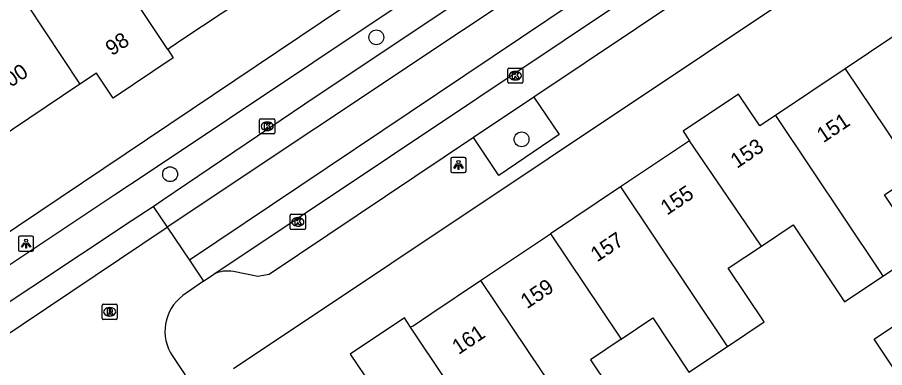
# Model space of a CAD drawing. Extents: x 158352 to 159489, y 383828 to 384597.
# Drawn here: x 158835 to 158892.1, y 384217.6 to 384240.7 of the extents above; entities that cross this region are included whole.
import ezdxf

# ---------------------------------------------------------------- set-up
doc = ezdxf.new("R2010")
doc.units = 0
for name, color, linetype in [('IMGEO_Boom', 7, 'Continuous'), ('IMGEO_Kolk', 7, 'Continuous'), ('IMGEO_Lichtpunt', 7, 'Continuous'), ('IMGEO_Pand', 7, 'Continuous'), ('IMGEO_Pand_nummerreeks', 7, 'Continuous'), ('IMGEO_Parkeervlak_open', 7, 'Continuous'), ('IMGEO_Rijbaan_lokaal_gesloten', 7, 'Continuous'), ('IMGEO_Rijbaan_lokaal_open', 7, 'Continuous'), ('IMGEO_Rioolput', 7, 'Continuous'), ('IMGEO_Voetpad_open', 7, 'Continuous')]:
    doc.layers.add(name, color=color, linetype=linetype)

msp = doc.modelspace()

# ---------------------------------------------------------------- linework, layer by layer
at = {"layer": 'IMGEO_Boom'}
for centre in [(158858.595, 384239.407), (158868.161, 384232.684), (158845.022, 384230.389)]:
    msp.add_circle(centre, 0.489, dxfattribs=at)
at = {"layer": 'IMGEO_Kolk'}
for p, q in [((158867.249, 384236.455), (158867.249, 384237.307)), ((158867.324, 384237.381), (158868.176, 384237.381)), ((158867.737, 384237.161), (158867.762, 384237.161)), ((158868.25, 384237.307), (158868.25, 384236.455)), ((158867.76, 384236.601), (158867.735, 384236.601)), ((158868.176, 384236.381), (158867.324, 384236.381)), ((158850.914, 384233.12), (158850.914, 384233.972)), ((158850.989, 384234.046), (158851.841, 384234.046)), ((158851.402, 384233.826), (158851.427, 384233.826)), ((158851.915, 384233.972), (158851.915, 384233.12)), ((158851.425, 384233.266), (158851.4, 384233.266)), ((158851.841, 384233.046), (158850.989, 384233.046)), ((158852.928, 384226.819), (158852.928, 384227.671)), ((158853.003, 384227.745), (158853.855, 384227.745)), ((158853.416, 384227.525), (158853.441, 384227.525)), ((158853.929, 384227.671), (158853.929, 384226.819)), ((158853.439, 384226.965), (158853.414, 384226.965)), ((158853.855, 384226.745), (158853.003, 384226.745))]:
    msp.add_line(p, q, dxfattribs=at)
for points in [[(158867.249, 384236.455), (158867.249, 384237.307)], [(158867.324, 384237.381), (158868.176, 384237.381)], [(158867.57, 384237.081), (158867.693, 384237.081), (158867.693, 384236.93), (158867.823, 384237.081), (158867.987, 384237.081), (158867.841, 384236.93), (158867.994, 384236.681), (158867.842, 384236.681), (158867.757, 384236.845), (158867.693, 384236.778), (158867.693, 384236.681), (158867.57, 384236.681), (158867.57, 384237.081)], [(158868.25, 384237.307), (158868.25, 384236.455)], [(158868.176, 384236.381), (158867.324, 384236.381)], [(158850.914, 384233.12), (158850.914, 384233.972)], [(158850.989, 384234.046), (158851.841, 384234.046)], [(158851.235, 384233.746), (158851.358, 384233.746), (158851.358, 384233.595), (158851.488, 384233.746), (158851.652, 384233.746), (158851.506, 384233.595), (158851.659, 384233.346), (158851.507, 384233.346), (158851.422, 384233.51), (158851.358, 384233.443), (158851.358, 384233.346), (158851.235, 384233.346), (158851.235, 384233.746)], [(158851.915, 384233.972), (158851.915, 384233.12)], [(158851.841, 384233.046), (158850.989, 384233.046)], [(158852.928, 384226.819), (158852.928, 384227.671)], [(158853.003, 384227.745), (158853.855, 384227.745)], [(158853.249, 384227.445), (158853.372, 384227.445), (158853.372, 384227.294), (158853.502, 384227.445), (158853.666, 384227.445), (158853.52, 384227.294), (158853.673, 384227.045), (158853.521, 384227.045), (158853.436, 384227.209), (158853.372, 384227.142), (158853.372, 384227.045), (158853.249, 384227.045), (158853.249, 384227.445)], [(158853.929, 384227.671), (158853.929, 384226.819)], [(158853.855, 384226.745), (158853.003, 384226.745)]]:
    msp.add_lwpolyline(points, dxfattribs=at)
for centre, start, end in [((158867.326, 384237.305), 91.552, 178.448), ((158867.326, 384237.305), 91.552, 178.448), ((158868.174, 384237.305), 1.552, 88.448), ((158868.174, 384237.305), 1.552, 88.448), ((158867.326, 384236.457), 181.552, 268.448), ((158867.326, 384236.457), 181.552, 268.448), ((158868.174, 384236.457), 271.552, 358.448), ((158868.174, 384236.457), 271.552, 358.448), ((158850.991, 384233.97), 91.552, 178.448), ((158850.991, 384233.97), 91.552, 178.448), ((158851.839, 384233.97), 1.552, 88.448), ((158851.839, 384233.97), 1.552, 88.448), ((158850.991, 384233.122), 181.552, 268.448), ((158850.991, 384233.122), 181.552, 268.448), ((158851.839, 384233.122), 271.552, 358.448), ((158851.839, 384233.122), 271.552, 358.448), ((158853.005, 384227.669), 91.552, 178.448), ((158853.005, 384227.669), 91.552, 178.448), ((158853.853, 384227.669), 1.552, 88.448), ((158853.853, 384227.669), 1.552, 88.448), ((158853.005, 384226.821), 181.552, 268.448), ((158853.005, 384226.821), 181.552, 268.448), ((158853.853, 384226.821), 271.552, 358.448), ((158853.853, 384226.821), 271.552, 358.448)]:
    msp.add_arc(centre, 0.0765, start, end, dxfattribs=at)
for centre, major_axis, ratio, start_param, end_param in [((158867.736, 384236.881), (-0.387, 0.002), 0.722429, 4.712389, 7.853982), ((158867.761, 384236.881), (-0.39, 0.002), 0.717154, 1.570796, 4.712389), ((158851.401, 384233.546), (-0.387, 0.002), 0.722429, 4.712389, 7.853982), ((158851.426, 384233.546), (-0.39, 0.002), 0.717154, 1.570796, 4.712389), ((158853.415, 384227.245), (-0.387, 0.002), 0.722429, 4.712389, 7.853982), ((158853.44, 384227.245), (-0.39, 0.002), 0.717154, 1.570796, 4.712389)]:
    msp.add_ellipse(centre, major_axis=major_axis, ratio=ratio, start_param=start_param, end_param=end_param, dxfattribs=at)
at = {"layer": 'IMGEO_Lichtpunt'}
for p, q in [((158863.51, 384231.398), (158863.51, 384230.591)), ((158863.51, 384231.398), (158863.51, 384230.591)), ((158864.412, 384231.493), (158863.604, 384231.493)), ((158864.412, 384231.493), (158863.604, 384231.493)), ((158864.506, 384230.591), (158864.506, 384231.398)), ((158864.506, 384230.591), (158864.506, 384231.398)), ((158863.604, 384230.497), (158864.412, 384230.497)), ((158863.604, 384230.497), (158864.412, 384230.497)), ((158835.036, 384226.212), (158835.036, 384225.405)), ((158835.036, 384226.212), (158835.036, 384225.405)), ((158835.938, 384226.307), (158835.13, 384226.307)), ((158835.938, 384226.307), (158835.13, 384226.307)), ((158836.032, 384225.405), (158836.032, 384226.212)), ((158836.032, 384225.405), (158836.032, 384226.212)), ((158835.13, 384225.311), (158835.938, 384225.311)), ((158835.13, 384225.311), (158835.938, 384225.311))]:
    msp.add_line(p, q, dxfattribs=at)
for points in [[(158863.884, 384231.062), (158863.923, 384231.034), (158863.735, 384230.772), (158863.697, 384230.799), (158863.884, 384231.062)], [(158863.986, 384231.014), (158864.033, 384231.014), (158864.033, 384230.692), (158863.986, 384230.692), (158863.986, 384231.014)], [(158864.096, 384231.034), (158864.134, 384231.061), (158864.321, 384230.799), (158864.282, 384230.771), (158864.096, 384231.034)], [(158835.41, 384225.876), (158835.449, 384225.848), (158835.261, 384225.586), (158835.223, 384225.613), (158835.41, 384225.876)], [(158835.512, 384225.828), (158835.559, 384225.828), (158835.559, 384225.506), (158835.512, 384225.506), (158835.512, 384225.828)], [(158835.622, 384225.848), (158835.66, 384225.875), (158835.847, 384225.613), (158835.808, 384225.585), (158835.622, 384225.848)]]:
    msp.add_lwpolyline(points, dxfattribs=at)
for centre in [(158864.009, 384231.196), (158835.535, 384226.01)]:
    msp.add_circle(centre, 0.0994, dxfattribs=at)
for centre, start, end in [((158863.604, 384231.398), 90, 180), ((158863.604, 384231.398), 90, 180), ((158864.412, 384231.398), 0, 90), ((158864.412, 384231.398), 0, 90), ((158863.604, 384230.591), 180, 270), ((158863.604, 384230.591), 180, 270), ((158864.412, 384230.591), 270, 0), ((158864.412, 384230.591), 270, 360), ((158835.13, 384226.212), 90, 180), ((158835.13, 384226.212), 90, 180), ((158835.938, 384226.212), 0, 90), ((158835.938, 384226.212), 0, 90), ((158835.13, 384225.405), 180, 270), ((158835.13, 384225.405), 180, 270), ((158835.938, 384225.405), 270, 0), ((158835.938, 384225.405), 270, 360)]:
    msp.add_arc(centre, 0.0946, start, end, dxfattribs=at)
at = {"layer": 'IMGEO_Pand'}
for points in [[(158832.074, 384246.881), (158839.085, 384236.32)], [(158844.858, 384238.609), (158840.338, 384245.418)], [(158849.731, 384241.867), (158845.861, 384239.28), (158845.017, 384238.715), (158844.858, 384238.609)], [(158894.087, 384240.426), (158889.48, 384237.342)], [(158844.858, 384238.609), (158845.229, 384238.05), (158841.271, 384235.391), (158840.161, 384237.042), (158839.085, 384236.32)], [(158889.48, 384237.342), (158884.873, 384234.258)], [(158889.48, 384237.342), (158893.973, 384230.631), (158894.123, 384230.406)], [(158839.085, 384236.32), (158833.473, 384232.558)], [(158884.873, 384234.258), (158883.855, 384233.577), (158882.455, 384235.669), (158878.797, 384233.22), (158879.219, 384232.59)], [(158884.873, 384234.258), (158891.756, 384223.975), (158891.961, 384223.669)], [(158879.219, 384232.59), (158874.68, 384229.551)], [(158883.96, 384225.655), (158883.857, 384225.809), (158879.219, 384232.59)], [(158891.961, 384223.669), (158894.496, 384225.366), (158892.051, 384229.019), (158894.123, 384230.406)], [(158874.68, 384229.551), (158870.073, 384226.467)], [(158874.68, 384229.551), (158881.64, 384219.152), (158881.717, 384219.038)], [(158883.96, 384225.655), (158886.038, 384227.045), (158889.431, 384221.975), (158891.961, 384223.669)], [(158865.465, 384223.383), (158870.073, 384226.467)], [(158870.073, 384226.467), (158874.595, 384219.711), (158874.72, 384219.524)], [(158881.717, 384219.038), (158884.14, 384220.66), (158881.776, 384224.193), (158883.96, 384225.655)], [(158860.858, 384220.299), (158861.016, 384220.405), (158862.19, 384221.191), (158865.465, 384223.383)], [(158865.465, 384223.383), (158871.557, 384214.283), (158872.492, 384212.886)], [(158860.858, 384220.299), (158860.447, 384220.913), (158856.885, 384218.53), (158858.292, 384216.428), (158857.246, 384215.728)], [(158874.72, 384219.524), (158876.795, 384220.913), (158879.185, 384217.343), (158881.717, 384219.038)], [(158895.499, 384218.383), (158898.48, 384213.932), (158896.151, 384212.372), (158893.17, 384216.823), (158891.373, 384219.507), (158893.703, 384221.067)], [(158865.517, 384213.338), (158865.421, 384213.482), (158860.858, 384220.299)], [(158874.72, 384219.524), (158872.692, 384218.166), (158875.07, 384214.612), (158874.875, 384214.481)]]:
    msp.add_lwpolyline(points, dxfattribs=at)
at = {"layer": 'IMGEO_Parkeervlak_open'}
msp.add_lwpolyline([(158868.973, 384235.474), (158864.997, 384232.808)], dxfattribs=at)
at = {"layer": 'IMGEO_Rijbaan_lokaal_gesloten'}
for points in [[(158928.875, 384277.975), (158927.924, 384279.398), (158875.348, 384244.245), (158846.287, 384224.725)], [(158847.89, 384223.805), (158928.741, 384277.867)], [(158843.894, 384228.271), (158844.531, 384228.697), (158853.892, 384235.025), (158913.401, 384274.791)], [(158913.401, 384274.791), (158914.324, 384273.367), (158910.948, 384271.094), (158874.134, 384246.446), (158844.821, 384226.897)], [(158831.156, 384219.806), (158832.496, 384220.707), (158842.526, 384227.357), (158843.894, 384228.271)], [(158843.894, 384228.271), (158844.821, 384226.897)], [(158832.123, 384218.384), (158844.821, 384226.897)], [(158847.222, 384223.339), (158847.89, 384223.805)]]:
    msp.add_lwpolyline(points, dxfattribs=at)
at = {"layer": 'IMGEO_Rijbaan_lokaal_open'}
for points in [[(158844.821, 384226.897), (158846.287, 384224.725)], [(158846.287, 384224.725), (158847.222, 384223.339)], [(158847.222, 384223.339), (158845.858, 384222.389)], [(158845.198, 384218.378), (158846.791, 384215.962)]]:
    msp.add_lwpolyline(points, dxfattribs=at)
msp.add_arc((158847.609, 384220.041), 2.929, 126.7155, 214.5962, dxfattribs=at)
at = {"layer": 'IMGEO_Rioolput'}
for p, q in [((158840.54, 384220.893), (158840.54, 384221.745)), ((158840.615, 384221.819), (158841.467, 384221.819)), ((158841.541, 384221.745), (158841.541, 384220.893)), ((158841.028, 384221.599), (158841.053, 384221.599)), ((158841.467, 384220.819), (158840.615, 384220.819)), ((158841.051, 384221.039), (158841.026, 384221.039))]:
    msp.add_line(p, q, dxfattribs=at)
for points in [[(158840.54, 384220.893), (158840.54, 384221.745)], [(158840.615, 384221.819), (158841.467, 384221.819)], [(158841.541, 384221.745), (158841.541, 384220.893)], [(158841.129, 384221.517), (158840.877, 384221.519), (158840.877, 384221.119)], [(158840.877, 384221.119), (158841.001, 384221.119), (158841.001, 384221.281), (158841.012, 384221.281)], [(158841.055, 384221.438), (158841.001, 384221.438), (158841.001, 384221.357)], [(158841.001, 384221.357), (158841.053, 384221.357)], [(158841.059, 384221.252), (158841.13, 384221.119), (158841.27, 384221.119), (158841.205, 384221.245)], [(158841.467, 384220.819), (158840.615, 384220.819)]]:
    msp.add_lwpolyline(points, dxfattribs=at)
for centre, radius, start, end in [((158840.617, 384221.743), 0.0765, 91.552, 178.448), ((158840.617, 384221.743), 0.0765, 91.552, 178.448), ((158841.465, 384221.743), 0.0765, 1.552, 88.448), ((158841.465, 384221.743), 0.0765, 1.552, 88.448), ((158841.011, 384221.228), 0.0533, 26.0293, 88.6989), ((158841.037, 384221.546), 0.19, 274.7715, 282.9687), ((158841.061, 384221.342), 0.0964, 77.0061, 93.1865), ((158841.075, 384221.399), 0.0378, 276.6634, 79.6772), ((158841.128, 384221.407), 0.109, 350.3612, 89.416), ((158841.126, 384221.407), 0.112, 277.5842, 350.9817), ((158841.11, 384221.192), 0.108, 29.5134, 73.7905), ((158840.617, 384220.895), 0.0765, 181.552, 268.448), ((158840.617, 384220.895), 0.0765, 181.552, 268.448), ((158841.465, 384220.895), 0.0765, 271.552, 358.448), ((158841.465, 384220.895), 0.0765, 271.552, 358.448)]:
    msp.add_arc(centre, radius, start, end, dxfattribs=at)
for centre, major_axis, ratio, start_param, end_param in [((158841.027, 384221.319), (-0.387, 0.002), 0.722429, 4.712389, 7.853982), ((158841.052, 384221.319), (-0.39, 0.002), 0.717154, 1.570796, 4.712389)]:
    msp.add_ellipse(centre, major_axis=major_axis, ratio=ratio, start_param=start_param, end_param=end_param, dxfattribs=at)
at = {"layer": 'IMGEO_Voetpad_open'}
for points in [[(158904.752, 384277.514), (158906.1, 384275.563), (158906.452, 384275.023), (158824.924, 384220.195), (158821.151, 384217.705), (158820.552, 384218.57), (158819.391, 384220.337)], [(158819.794, 384214.568), (158822.229, 384216.216), (158829.341, 384221.029), (158831.356, 384222.372), (158841.384, 384229.054), (158843.37, 384230.376), (158909.63, 384274.668)], [(158849.203, 384217.574), (158932.003, 384272.919)], [(158882.481, 384244.532), (158868.973, 384235.474)], [(158868.973, 384235.474), (158870.636, 384233.002), (158866.676, 384230.311), (158864.997, 384232.808)], [(158864.997, 384232.808), (158851.545, 384223.788), (158850.787, 384223.65), (158849.183, 384223.967)]]:
    msp.add_lwpolyline(points, dxfattribs=at)
msp.add_arc((158848.777, 384221.968), 2.04, 78.514, 115.7688, dxfattribs=at)

# ---------------------------------------------------------------- texts
at = {"layer": 'IMGEO_Pand_nummerreeks'}
for s, rotation, p in [('98', 33.8332, (158841.187, 384238.153)), ('100', 33.8332, (158833.91, 384235.666)), ('151', 33.7976, (158888.027, 384232.421)), ('153', 33.7982, (158882.346, 384230.736)), ('155', 33.7982, (158877.739, 384227.652)), ('157', 33.7982, (158873.132, 384224.568)), ('159', 33.7988, (158868.524, 384221.484)), ('161', 33.7988, (158864.011, 384218.464))]:
    msp.add_text(s, height=1, rotation=rotation, dxfattribs=at).set_placement(p)

doc.saveas('drawing.dxf')
